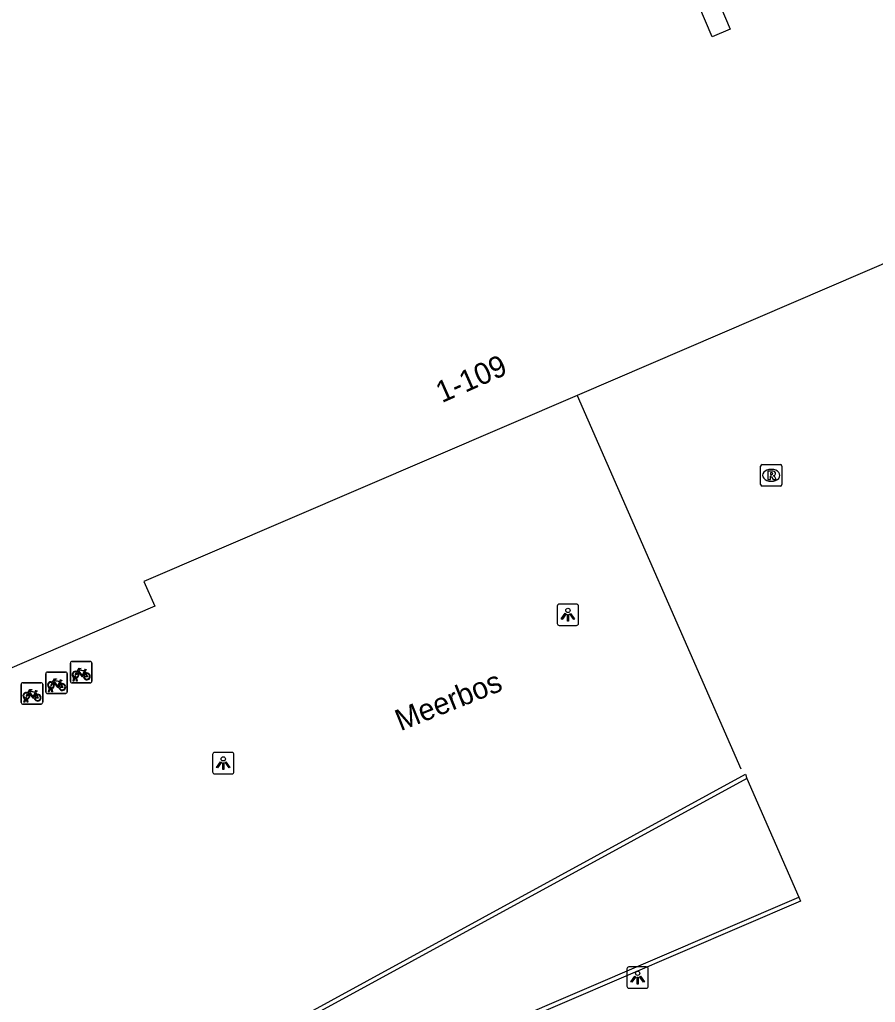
# Model space of a CAD drawing. Extents: x 155640 to 156810, y 382822 to 384046.
# Drawn here: x 156568.03 to 156607.94, y 383743.57 to 383789.39 of the extents above; entities that cross this region are included whole.
import ezdxf

# ---------------------------------------------------------------- set-up
doc = ezdxf.new("R2010")
doc.units = 0
for name, color, linetype in [('IMGEO_Fietsenrek', 7, 'Continuous'), ('IMGEO_Lichtpunt', 7, 'Continuous'), ('IMGEO_Lijnafwatering', 7, 'Continuous'), ('IMGEO_Muur', 7, 'Continuous'), ('IMGEO_Openbare_ruimte_label', 7, 'Continuous'), ('IMGEO_Pand', 7, 'Continuous'), ('IMGEO_Pand_nummerreeks', 7, 'Continuous'), ('IMGEO_Rijbaan_lokaal_gesloten', 7, 'Continuous'), ('IMGEO_Rioolput', 7, 'Continuous')]:
    doc.layers.add(name, color=color, linetype=linetype)

msp = doc.modelspace()

# ---------------------------------------------------------------- linework, layer by layer
at = {"layer": 'IMGEO_Fietsenrek'}
for p, q in [((156570.401, 383758.542), (156570.401, 383759.383)), ((156570.401, 383759.383), (156570.401, 383758.542)), ((156570.476, 383759.467), (156571.317, 383759.467)), ((156571.317, 383759.467), (156570.476, 383759.467)), ((156571.401, 383759.392), (156571.401, 383758.551)), ((156571.401, 383758.551), (156571.401, 383759.392)), ((156569.254, 383758.046), (156569.254, 383758.887)), ((156569.254, 383758.887), (156569.254, 383758.046)), ((156569.329, 383758.971), (156570.17, 383758.971)), ((156570.17, 383758.971), (156569.329, 383758.971)), ((156570.254, 383758.896), (156570.254, 383758.055)), ((156570.254, 383758.055), (156570.254, 383758.896)), ((156570.528, 383758.551), (156570.567, 383758.711)), ((156570.597, 383758.699), (156570.562, 383758.551)), ((156570.639, 383758.723), (156570.638, 383758.727)), ((156570.68, 383758.551), (156570.646, 383758.693)), ((156570.67, 383758.734), (156570.671, 383758.727)), ((156570.678, 383758.697), (156570.713, 383758.551)), ((156571.088, 383759.016), (156571.124, 383758.921)), ((156568.107, 383757.55), (156568.107, 383758.391)), ((156568.107, 383758.391), (156568.107, 383757.55)), ((156568.182, 383758.475), (156569.023, 383758.475)), ((156569.023, 383758.475), (156568.182, 383758.475)), ((156569.107, 383758.4), (156569.107, 383757.559)), ((156569.107, 383757.559), (156569.107, 383758.4)), ((156569.381, 383758.055), (156569.42, 383758.215)), ((156569.45, 383758.203), (156569.415, 383758.055)), ((156569.492, 383758.227), (156569.491, 383758.231)), ((156569.533, 383758.055), (156569.499, 383758.197)), ((156569.523, 383758.238), (156569.524, 383758.231)), ((156569.531, 383758.201), (156569.566, 383758.055)), ((156569.941, 383758.52), (156569.977, 383758.425)), ((156571.326, 383758.467), (156570.485, 383758.467)), ((156570.485, 383758.467), (156571.326, 383758.467)), ((156570.562, 383758.551), (156570.528, 383758.551)), ((156570.713, 383758.551), (156570.68, 383758.551)), ((156568.234, 383757.559), (156568.273, 383757.719)), ((156568.303, 383757.707), (156568.268, 383757.559)), ((156568.345, 383757.731), (156568.344, 383757.735)), ((156568.386, 383757.559), (156568.352, 383757.701)), ((156568.376, 383757.742), (156568.377, 383757.735)), ((156568.384, 383757.705), (156568.419, 383757.559)), ((156568.794, 383758.024), (156568.83, 383757.929)), ((156570.179, 383757.971), (156569.338, 383757.971)), ((156569.338, 383757.971), (156570.179, 383757.971)), ((156569.415, 383758.055), (156569.381, 383758.055)), ((156569.566, 383758.055), (156569.533, 383758.055)), ((156569.032, 383757.475), (156568.191, 383757.475)), ((156568.191, 383757.475), (156569.032, 383757.475)), ((156568.268, 383757.559), (156568.234, 383757.559)), ((156568.419, 383757.559), (156568.386, 383757.559))]:
    msp.add_line(p, q, dxfattribs=at)
for points in [[(156570.714, 383758.993), (156570.809, 383759.157), (156570.895, 383759.143), (156570.897, 383759.134), (156570.841, 383759.123), (156570.814, 383759.078), (156571.07, 383759.037)], [(156571.057, 383759.012), (156570.8, 383759.053), (156570.783, 383759.024), (156570.95, 383758.804), (156571.057, 383759.012)], [(156571.07, 383759.037), (156571.095, 383759.086), (156571.089, 383759.09), (156571.066, 383759.094), (156571.054, 383759.101), (156571.053, 383759.104), (156571.055, 383759.109), (156571.15, 383759.094), (156571.152, 383759.084), (156571.142, 383759.071), (156571.13, 383759.065), (156571.116, 383759.071), (156571.088, 383759.016)], [(156569.567, 383758.497), (156569.662, 383758.661), (156569.748, 383758.647), (156569.75, 383758.638), (156569.694, 383758.627), (156569.667, 383758.582), (156569.923, 383758.541)], [(156569.923, 383758.541), (156569.948, 383758.59), (156569.942, 383758.594), (156569.919, 383758.598), (156569.907, 383758.605), (156569.906, 383758.608), (156569.908, 383758.613), (156570.003, 383758.598), (156570.005, 383758.588), (156569.995, 383758.575), (156569.983, 383758.569), (156569.969, 383758.575), (156569.941, 383758.52)], [(156570.735, 383758.941), (156570.683, 383758.851), (156570.643, 383758.826), (156570.644, 383758.873), (156570.699, 383758.967)], [(156571.01, 383758.749), (156570.96, 383758.749), (156570.769, 383759), (156570.75, 383758.968)], [(156571.105, 383758.914), (156571.075, 383758.991), (156570.966, 383758.773), (156571.009, 383758.773)], [(156571.039, 383758.773), (156571.159, 383758.772), (156571.115, 383758.886)], [(156571.135, 383758.893), (156571.19, 383758.748), (156571.04, 383758.748)], [(156568.42, 383758.001), (156568.515, 383758.165), (156568.601, 383758.151), (156568.603, 383758.142), (156568.547, 383758.131), (156568.52, 383758.086), (156568.776, 383758.045)], [(156568.776, 383758.045), (156568.801, 383758.094), (156568.795, 383758.098), (156568.772, 383758.102), (156568.76, 383758.109), (156568.759, 383758.112), (156568.761, 383758.117), (156568.856, 383758.102), (156568.858, 383758.092), (156568.848, 383758.079), (156568.836, 383758.073), (156568.822, 383758.079), (156568.794, 383758.024)], [(156569.588, 383758.445), (156569.536, 383758.355), (156569.496, 383758.33), (156569.497, 383758.377), (156569.552, 383758.471)], [(156569.863, 383758.253), (156569.813, 383758.253), (156569.622, 383758.504), (156569.603, 383758.472)], [(156569.91, 383758.516), (156569.653, 383758.557), (156569.636, 383758.528), (156569.803, 383758.308), (156569.91, 383758.516)], [(156569.958, 383758.418), (156569.928, 383758.495), (156569.819, 383758.277), (156569.862, 383758.277)], [(156569.892, 383758.277), (156570.012, 383758.276), (156569.968, 383758.39)], [(156569.988, 383758.397), (156570.043, 383758.252), (156569.893, 383758.252)], [(156568.441, 383757.949), (156568.389, 383757.859), (156568.349, 383757.834), (156568.35, 383757.881), (156568.405, 383757.975)], [(156568.716, 383757.757), (156568.666, 383757.757), (156568.475, 383758.008), (156568.456, 383757.976)], [(156568.763, 383758.02), (156568.506, 383758.061), (156568.489, 383758.032), (156568.656, 383757.812), (156568.763, 383758.02)], [(156568.811, 383757.922), (156568.781, 383757.999), (156568.672, 383757.781), (156568.715, 383757.781)], [(156568.745, 383757.781), (156568.865, 383757.78), (156568.821, 383757.894)], [(156568.841, 383757.901), (156568.896, 383757.756), (156568.746, 383757.756)]]:
    msp.add_lwpolyline(points, dxfattribs=at)
for centre, radius, start, end in [((156570.479, 383759.389), 0.0779, 92.4484, 184.2845), ((156570.479, 383759.389), 0.0779, 92.4484, 184.2845), ((156571.323, 383759.389), 0.0779, 2.4484, 94.2845), ((156571.323, 383759.389), 0.0779, 2.4484, 94.2845), ((156569.332, 383758.893), 0.0779, 92.4484, 184.2845), ((156569.332, 383758.893), 0.0779, 92.4484, 184.2845), ((156570.176, 383758.893), 0.0779, 2.4484, 94.2845), ((156570.176, 383758.893), 0.0779, 2.4484, 94.2845), ((156570.641, 383758.852), 0.159, 62.6766, 242.1369), ((156570.641, 383758.852), 0.129, 63.3192, 238.903), ((156570.621, 383758.723), 0.0499, 12.8025, 158.6934), ((156570.641, 383758.852), 0.159, 253.9967, 271.7867), ((156570.621, 383758.723), 0.0174, 12.8025, 163.4502), ((156570.641, 383758.852), 0.129, 253.415, 269.0204), ((156570.641, 383758.852), 0.129, 283.6043, 43.4302), ((156570.641, 383758.852), 0.159, 283.5766, 46.6042), ((156571.168, 383758.768), 0.159, 113.3408, 178.3217), ((156571.168, 383758.768), 0.159, 187.0065, 105.7708), ((156571.168, 383758.768), 0.129, 113.923, 177.9556), ((156571.168, 383758.768), 0.129, 188.6715, 104.5883), ((156568.185, 383758.397), 0.0779, 92.4484, 184.2845), ((156568.185, 383758.397), 0.0779, 92.4484, 184.2845), ((156569.029, 383758.397), 0.0779, 2.4484, 94.2845), ((156569.029, 383758.397), 0.0779, 2.4484, 94.2845), ((156569.494, 383758.356), 0.159, 62.6766, 242.1369), ((156569.494, 383758.356), 0.129, 63.3192, 238.903), ((156569.474, 383758.227), 0.0499, 12.8025, 158.6934), ((156569.494, 383758.356), 0.159, 253.9967, 271.7867), ((156569.474, 383758.227), 0.0174, 12.8025, 163.4502), ((156569.494, 383758.356), 0.129, 253.415, 269.0204), ((156569.494, 383758.356), 0.129, 283.6043, 43.4302), ((156569.494, 383758.356), 0.159, 283.5766, 46.6042), ((156570.021, 383758.272), 0.159, 113.3408, 178.3217), ((156570.021, 383758.272), 0.159, 187.0065, 105.7708), ((156570.021, 383758.272), 0.129, 113.923, 177.9556), ((156570.021, 383758.272), 0.129, 188.6715, 104.5883), ((156570.479, 383758.545), 0.0779, 182.4484, 274.2845), ((156570.479, 383758.545), 0.0779, 182.4484, 274.2845), ((156571.323, 383758.545), 0.0779, 272.4484, 4.2845), ((156571.323, 383758.545), 0.0779, 272.4484, 4.2845), ((156568.347, 383757.86), 0.159, 62.6766, 242.1369), ((156568.347, 383757.86), 0.129, 63.3192, 238.903), ((156568.327, 383757.731), 0.0499, 12.8025, 158.6934), ((156568.347, 383757.86), 0.159, 253.9967, 271.7867), ((156568.327, 383757.731), 0.0174, 12.8025, 163.4502), ((156568.347, 383757.86), 0.129, 253.415, 269.0204), ((156568.347, 383757.86), 0.129, 283.6043, 43.4302), ((156568.347, 383757.86), 0.159, 283.5766, 46.6042), ((156568.874, 383757.776), 0.159, 113.3408, 178.3217), ((156568.874, 383757.776), 0.159, 187.0065, 105.7708), ((156568.874, 383757.776), 0.129, 113.923, 177.9556), ((156568.874, 383757.776), 0.129, 188.6715, 104.5883), ((156569.332, 383758.049), 0.0779, 182.4484, 274.2845), ((156569.332, 383758.049), 0.0779, 182.4484, 274.2845), ((156570.176, 383758.049), 0.0779, 272.4484, 4.2845), ((156570.176, 383758.049), 0.0779, 272.4484, 4.2845), ((156568.185, 383757.553), 0.0779, 182.4484, 274.2845), ((156568.185, 383757.553), 0.0779, 182.4484, 274.2845), ((156569.029, 383757.553), 0.0779, 272.4484, 4.2845), ((156569.029, 383757.553), 0.0779, 272.4484, 4.2845)]:
    msp.add_arc(centre, radius, start, end, dxfattribs=at)
at = {"layer": 'IMGEO_Lichtpunt'}
for p, q in [((156593.102, 383762.046), (156593.102, 383761.239)), ((156593.102, 383762.046), (156593.102, 383761.239)), ((156594.004, 383762.141), (156593.196, 383762.141)), ((156594.004, 383762.141), (156593.196, 383762.141)), ((156594.098, 383761.239), (156594.098, 383762.046)), ((156594.098, 383761.239), (156594.098, 383762.046)), ((156593.196, 383761.145), (156594.004, 383761.145)), ((156593.196, 383761.145), (156594.004, 383761.145)), ((156577.031, 383755.126), (156577.031, 383754.319)), ((156577.031, 383755.126), (156577.031, 383754.319)), ((156577.933, 383755.221), (156577.125, 383755.221)), ((156577.933, 383755.221), (156577.125, 383755.221)), ((156578.027, 383754.319), (156578.027, 383755.126)), ((156578.027, 383754.319), (156578.027, 383755.126)), ((156577.125, 383754.225), (156577.933, 383754.225)), ((156577.125, 383754.225), (156577.933, 383754.225)), ((156596.355, 383745.13), (156596.355, 383744.323)), ((156596.355, 383745.13), (156596.355, 383744.323)), ((156597.257, 383745.225), (156596.449, 383745.225)), ((156597.257, 383745.225), (156596.449, 383745.225)), ((156597.351, 383744.323), (156597.351, 383745.13)), ((156597.351, 383744.323), (156597.351, 383745.13)), ((156596.449, 383744.229), (156597.257, 383744.229)), ((156596.449, 383744.229), (156597.257, 383744.229))]:
    msp.add_line(p, q, dxfattribs=at)
for points in [[(156593.476, 383761.71), (156593.515, 383761.682), (156593.327, 383761.42), (156593.289, 383761.447), (156593.476, 383761.71)], [(156593.578, 383761.662), (156593.625, 383761.662), (156593.625, 383761.34), (156593.578, 383761.34), (156593.578, 383761.662)], [(156593.688, 383761.682), (156593.726, 383761.709), (156593.913, 383761.447), (156593.874, 383761.419), (156593.688, 383761.682)], [(156577.405, 383754.79), (156577.444, 383754.762), (156577.256, 383754.5), (156577.218, 383754.527), (156577.405, 383754.79)], [(156577.507, 383754.742), (156577.554, 383754.742), (156577.554, 383754.42), (156577.507, 383754.42), (156577.507, 383754.742)], [(156577.617, 383754.762), (156577.655, 383754.789), (156577.842, 383754.527), (156577.803, 383754.499), (156577.617, 383754.762)], [(156596.729, 383744.794), (156596.768, 383744.766), (156596.58, 383744.504), (156596.542, 383744.531), (156596.729, 383744.794)], [(156596.831, 383744.746), (156596.878, 383744.746), (156596.878, 383744.424), (156596.831, 383744.424), (156596.831, 383744.746)], [(156596.941, 383744.766), (156596.979, 383744.793), (156597.166, 383744.531), (156597.127, 383744.503), (156596.941, 383744.766)]]:
    msp.add_lwpolyline(points, dxfattribs=at)
for centre in [(156593.601, 383761.844), (156577.53, 383754.924), (156596.854, 383744.928)]:
    msp.add_circle(centre, 0.0994, dxfattribs=at)
for centre, start, end in [((156593.196, 383762.046), 90, 180), ((156593.196, 383762.046), 90, 180), ((156594.004, 383762.046), 0, 90), ((156594.004, 383762.046), 0, 90), ((156593.196, 383761.239), 180, 270), ((156593.196, 383761.239), 180, 270), ((156594.004, 383761.239), 270, 0), ((156594.004, 383761.239), 270, 360), ((156577.125, 383755.126), 90, 180), ((156577.125, 383755.126), 90, 180), ((156577.933, 383755.126), 0, 90), ((156577.933, 383755.126), 0, 90), ((156577.125, 383754.319), 180, 270), ((156577.125, 383754.319), 180, 270), ((156577.933, 383754.319), 270, 0), ((156577.933, 383754.319), 270, 360), ((156596.449, 383745.13), 90, 180), ((156596.449, 383745.13), 90, 180), ((156597.257, 383745.13), 0, 90), ((156597.257, 383745.13), 0, 90), ((156596.449, 383744.323), 180, 270), ((156596.449, 383744.323), 180, 270), ((156597.257, 383744.323), 270, 0), ((156597.257, 383744.323), 270, 360)]:
    msp.add_arc(centre, 0.0946, start, end, dxfattribs=at)
at = {"layer": 'IMGEO_Lijnafwatering'}
msp.add_lwpolyline([(156594.027, 383771.874), (156601.667, 383754.457)], dxfattribs=at)
at = {"layer": 'IMGEO_Muur'}
for points in [[(156604.369, 383748.474), (156604.442, 383748.29), (156576.93, 383736.468), (156575.502, 383739.801), (156601.883, 383754.203), (156601.947, 383754.015)], [(156601.947, 383754.015), (156575.768, 383739.721), (156577.022, 383736.736), (156604.369, 383748.474)]]:
    msp.add_lwpolyline(points, dxfattribs=at)
at = {"layer": 'IMGEO_Pand'}
for points in [[(156619.306, 383814.422), (156620.197, 383799.996), (156597.327, 383798.583), (156599.334, 383793.861), (156599.125, 383793.772), (156601.176, 383788.945), (156600.332, 383788.586), (156594.507, 383802.295), (156565.638, 383800.613), (156545.7, 383792.039), (156538.063, 383809.8)], [(156614.281, 383780.732), (156614.339, 383780.597), (156609.111, 383778.352), (156594.027, 383771.874), (156573.827, 383763.199), (156574.331, 383762.04), (156546.096, 383749.871), (156540.541, 383762.779)]]:
    msp.add_lwpolyline(points, dxfattribs=at)
at = {"layer": 'IMGEO_Rijbaan_lokaal_gesloten'}
msp.add_lwpolyline([(156601.947, 383754.015), (156604.369, 383748.474)], dxfattribs=at)
at = {"layer": 'IMGEO_Rioolput'}
for p, q in [((156602.584, 383767.718), (156602.584, 383768.57)), ((156602.659, 383768.644), (156603.511, 383768.644)), ((156603.072, 383768.424), (156603.097, 383768.424)), ((156603.585, 383768.57), (156603.585, 383767.718)), ((156603.095, 383767.864), (156603.07, 383767.864)), ((156603.511, 383767.644), (156602.659, 383767.644))]:
    msp.add_line(p, q, dxfattribs=at)
for points in [[(156602.584, 383767.718), (156602.584, 383768.57)], [(156602.659, 383768.644), (156603.511, 383768.644)], [(156603.173, 383768.342), (156602.921, 383768.344), (156602.921, 383767.944)], [(156603.099, 383768.263), (156603.045, 383768.263), (156603.045, 383768.182)], [(156603.585, 383768.57), (156603.585, 383767.718)], [(156602.921, 383767.944), (156603.045, 383767.944), (156603.045, 383768.106), (156603.056, 383768.106)], [(156603.045, 383768.182), (156603.097, 383768.182)], [(156603.103, 383768.077), (156603.174, 383767.944), (156603.314, 383767.944), (156603.249, 383768.07)], [(156603.511, 383767.644), (156602.659, 383767.644)]]:
    msp.add_lwpolyline(points, dxfattribs=at)
for centre, radius, start, end in [((156602.661, 383768.568), 0.0765, 91.552, 178.448), ((156602.661, 383768.568), 0.0765, 91.552, 178.448), ((156603.105, 383768.167), 0.0964, 77.0061, 93.1865), ((156603.119, 383768.224), 0.0378, 276.6634, 79.6772), ((156603.172, 383768.232), 0.109, 350.3612, 89.416), ((156603.17, 383768.232), 0.112, 277.5842, 350.9817), ((156603.509, 383768.568), 0.0765, 1.552, 88.448), ((156603.509, 383768.568), 0.0765, 1.552, 88.448), ((156603.055, 383768.053), 0.0533, 26.0293, 88.6989), ((156603.081, 383768.371), 0.19, 274.7715, 282.9687), ((156603.154, 383768.017), 0.108, 29.5134, 73.7905), ((156602.661, 383767.72), 0.0765, 181.552, 268.448), ((156602.661, 383767.72), 0.0765, 181.552, 268.448), ((156603.509, 383767.72), 0.0765, 271.552, 358.448), ((156603.509, 383767.72), 0.0765, 271.552, 358.448)]:
    msp.add_arc(centre, radius, start, end, dxfattribs=at)
for centre, major_axis, ratio, start_param, end_param in [((156603.071, 383768.144), (-0.387, 0.002), 0.722429, 4.712389, 7.853982), ((156603.096, 383768.144), (-0.39, 0.002), 0.717154, 1.570796, 4.712389)]:
    msp.add_ellipse(centre, major_axis=major_axis, ratio=ratio, start_param=start_param, end_param=end_param, dxfattribs=at)

# ---------------------------------------------------------------- texts
at = {"layer": 'IMGEO_Openbare_ruimte_label'}
msp.add_text('Meerbos', height=1, rotation=21.844, dxfattribs=at).set_placement((156585.795, 383756.206))
at = {"layer": 'IMGEO_Pand_nummerreeks'}
msp.add_text('1-109', height=1, rotation=23.8981, dxfattribs=at).set_placement((156587.724, 383771.506))

doc.saveas('drawing.dxf')
